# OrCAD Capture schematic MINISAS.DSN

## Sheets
1 PAGE2: size B; title: TIDA-00425; rev: A; note: 12 Gbps SAS-3 Link Extender
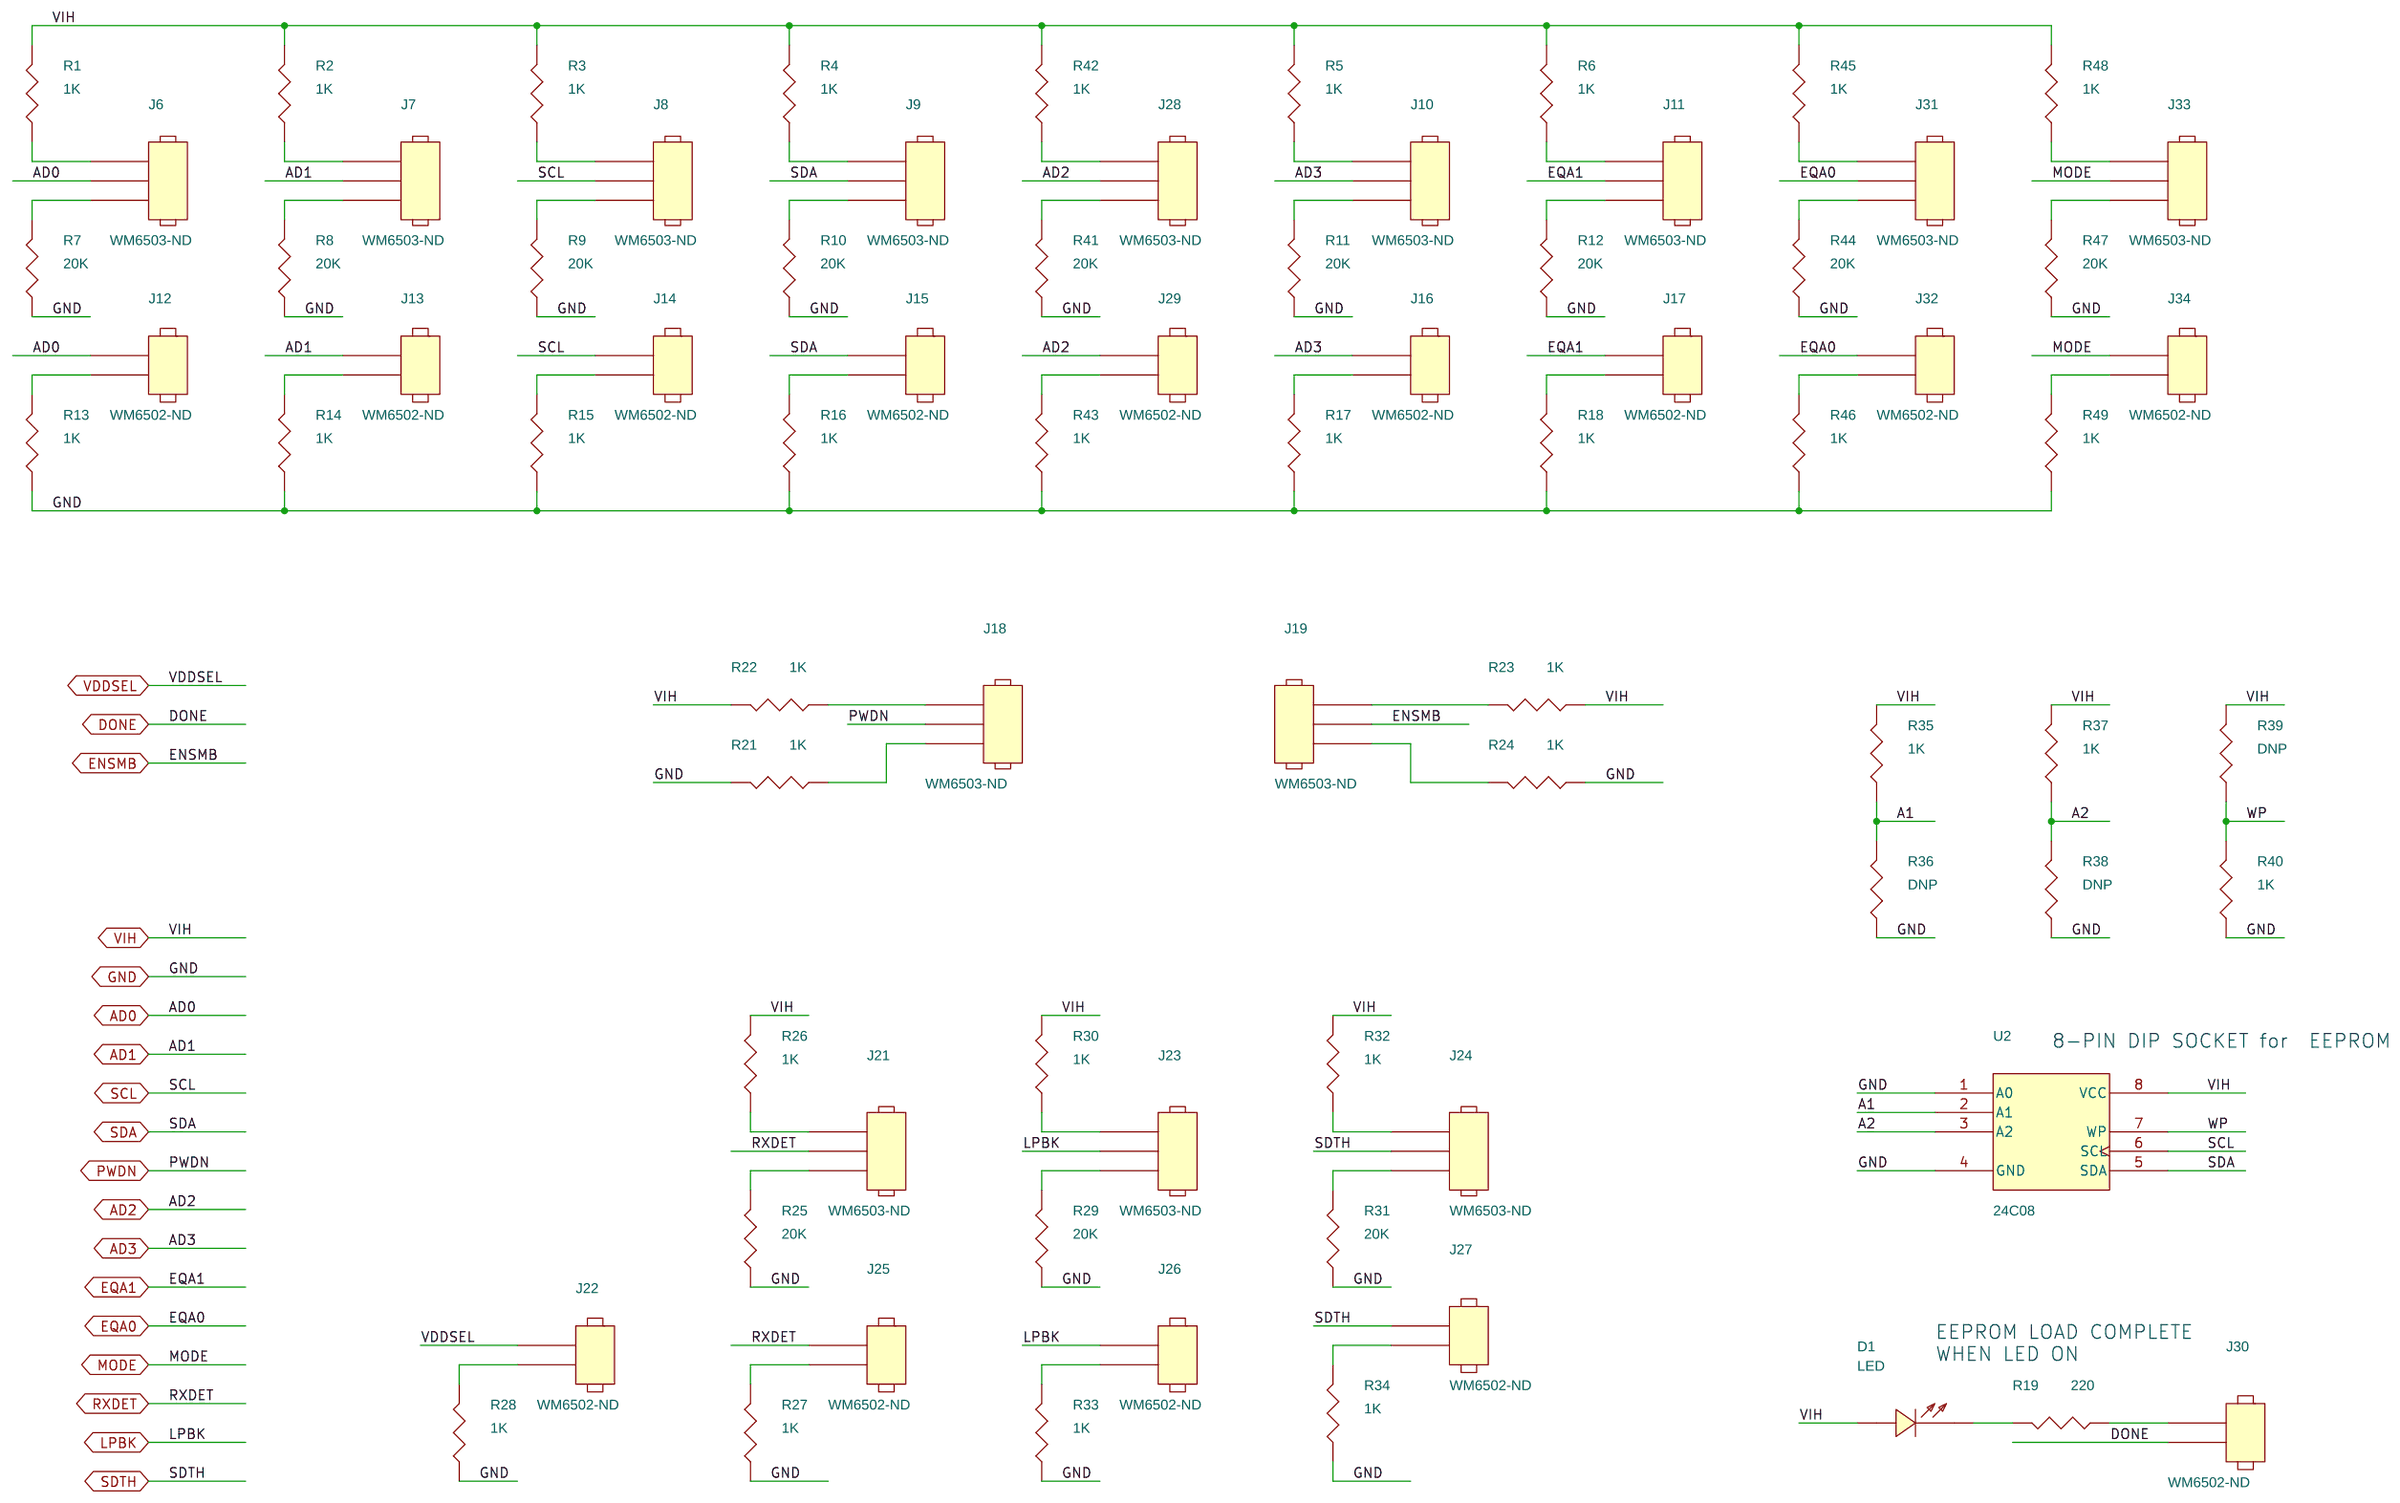
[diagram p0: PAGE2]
2 PAGE1: size B
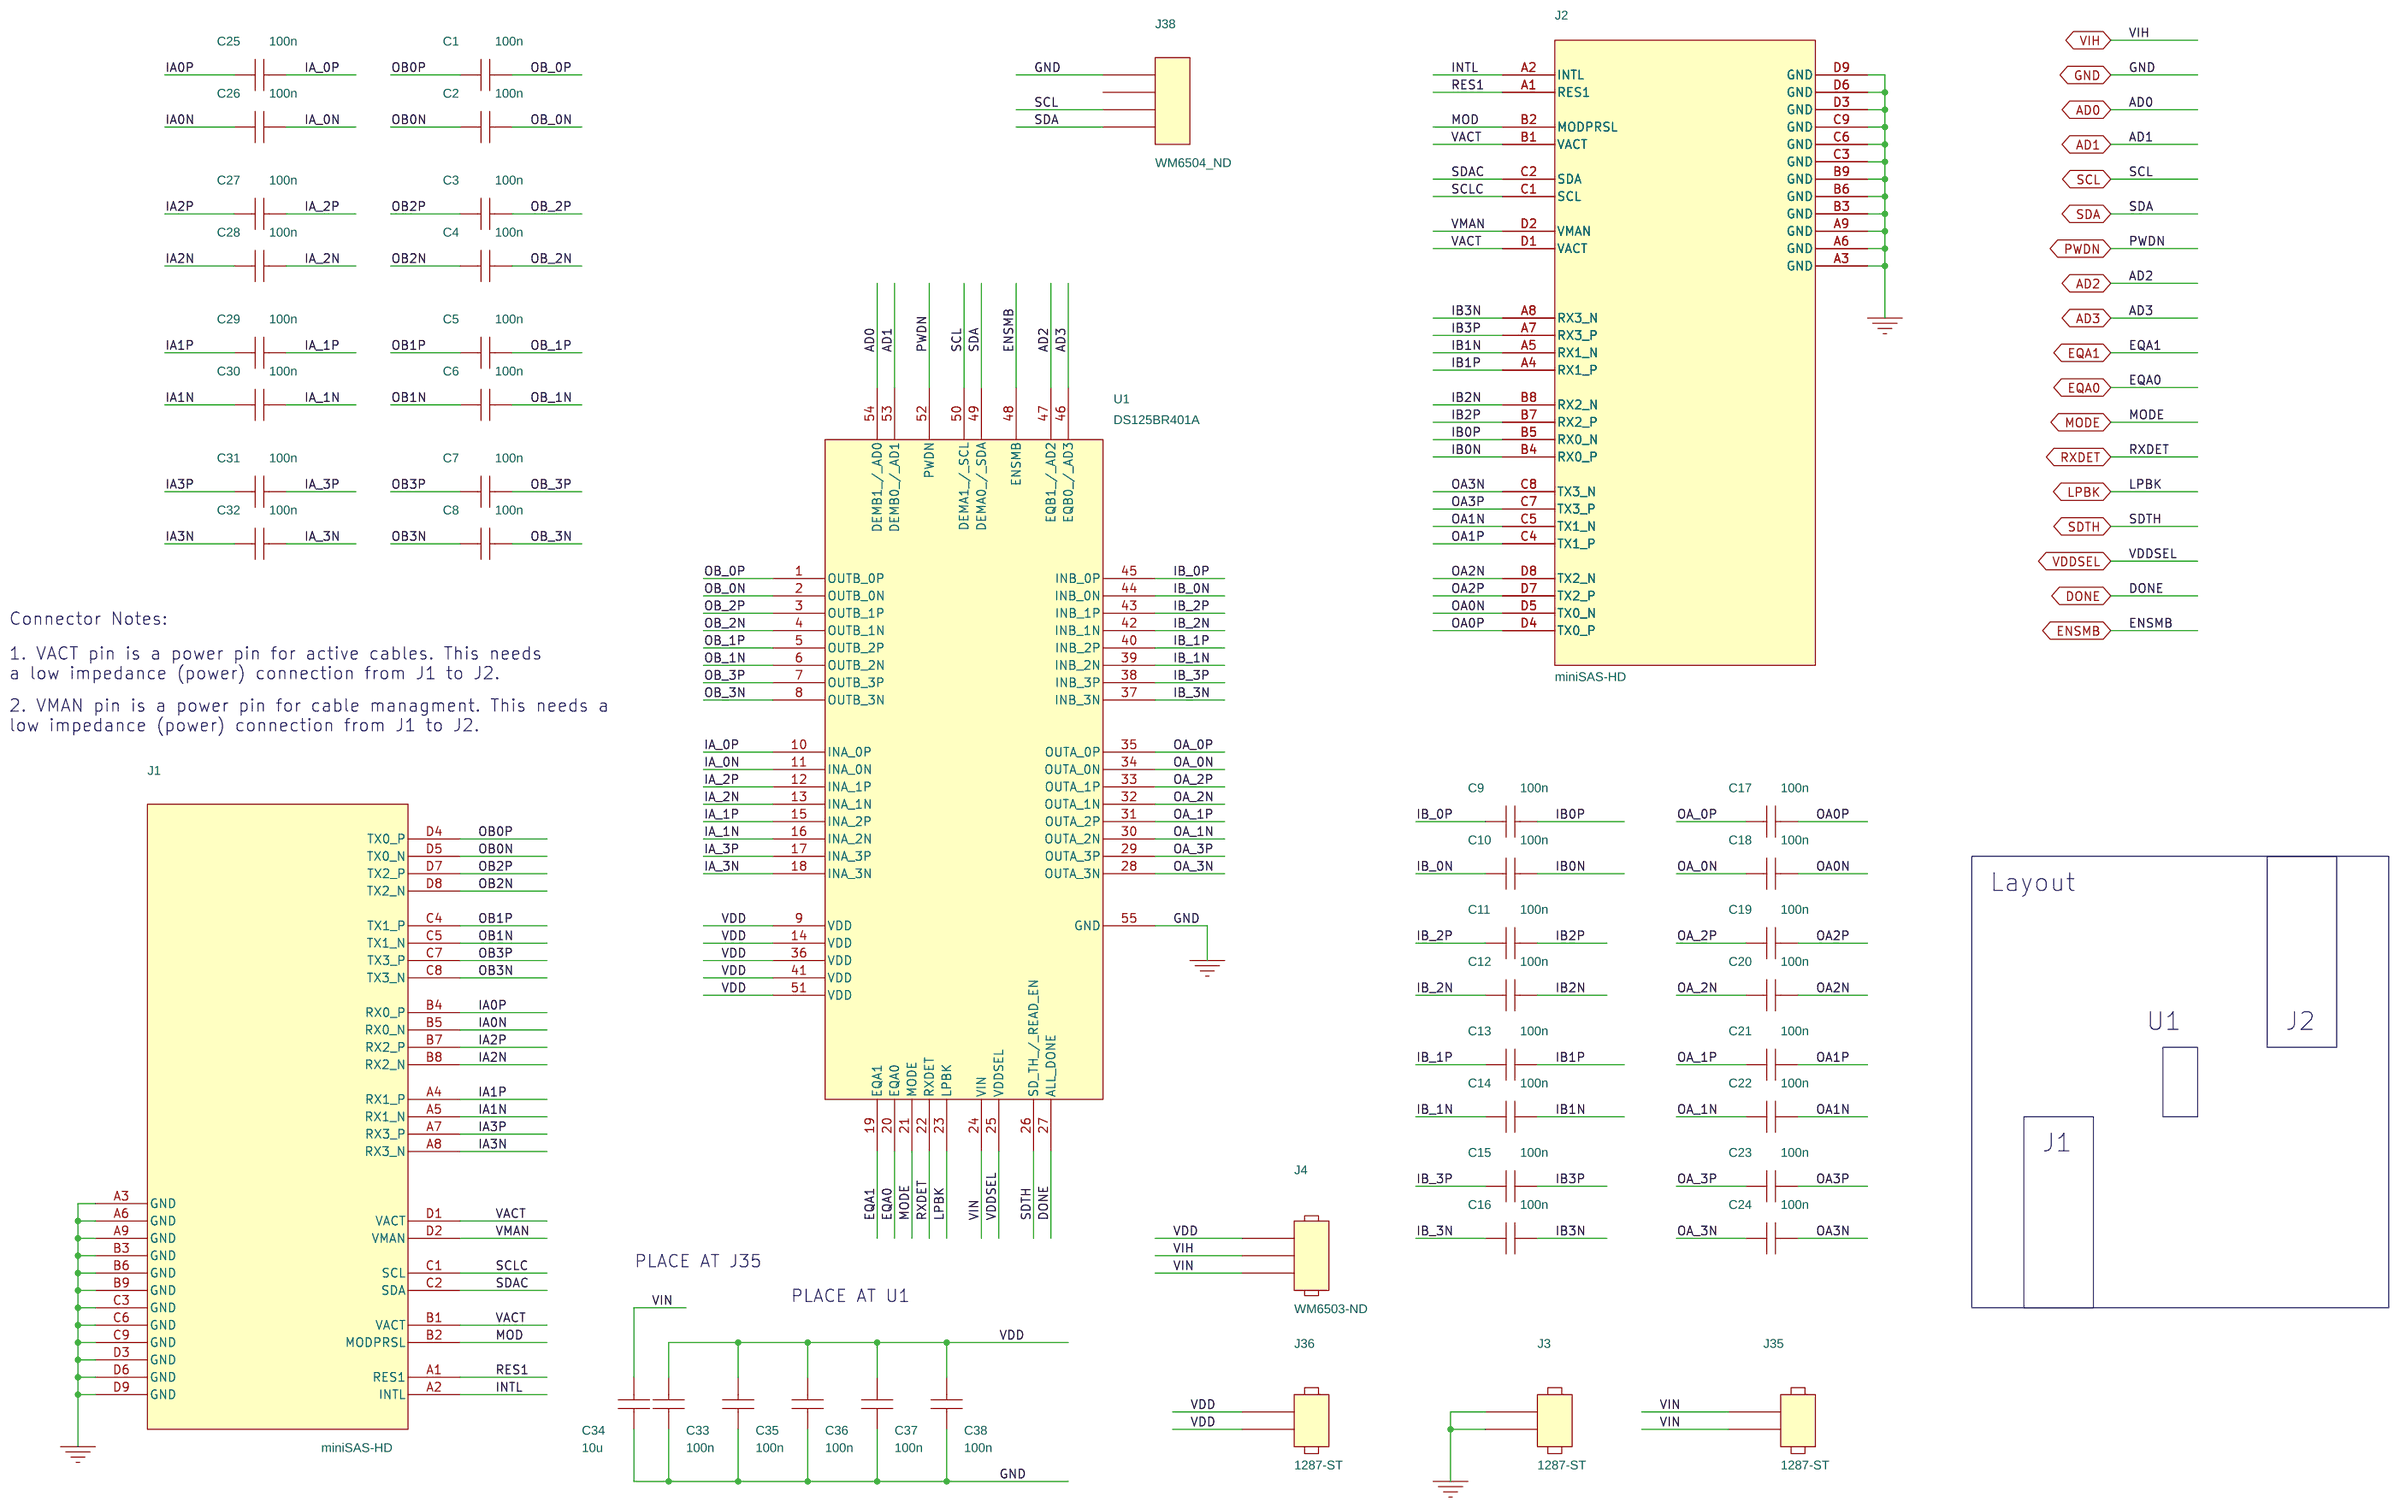
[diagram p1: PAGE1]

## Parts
sheet PAGE1
C1  100n  [0201]
C2  100n  [0201]
C3  100n  [0201]
C4  100n  [0201]
C5  100n  [0201]
C6  100n  [0201]
C7  100n  [0201]
C8  100n  [0201]
C9  100n  [0201]
C10  100n  [0201]
C11  100n  [0201]
C12  100n  [0201]
C13  100n  [0201]
C14  100n  [0201]
C15  100n  [0201]
C16  100n  [0201]
C17  100n  [0201]
C18  100n  [0201]
C19  100n  [0201]
C20  100n  [0201]
C21  100n  [0201]
C22  100n  [0201]
C23  100n  [0201]
C24  100n  [0201]
C25  100n  [0201]
C26  100n  [0201]
C27  100n  [0201]
C28  100n  [0201]
C29  100n  [0201]
C30  100n  [0201]
C31  100n  [0201]
C32  100n  [0201]
C33  100n  [0201]
C34  10u  [1206]
C35  100n  [0201]
C36  100n  [0201]
C37  100n  [0201]
C38  100n  [0201]
J1  miniSAS-HD  [minisashd]
J2  miniSAS-HD  [minisashd]
J3  1287-ST  [1287ST]
J4  WM6503-ND  [HEADER3]
J35  1287-ST  [1287ST]
J36  1287-ST  [1287ST]
J38  WM6504_ND  [HEADER4]
U1  DS125BR401A  [QFN54]
sheet PAGE2
D1  LED  [0603]
J6  WM6503-ND  [HEADER3]
J7  WM6503-ND  [HEADER3]
J8  WM6503-ND  [HEADER3]
J9  WM6503-ND  [HEADER3]
J10  WM6503-ND  [HEADER3]
J11  WM6503-ND  [HEADER3]
J12  WM6502-ND  [HEADER2]
J13  WM6502-ND  [HEADER2]
J14  WM6502-ND  [HEADER2]
J15  WM6502-ND  [HEADER2]
J16  WM6502-ND  [HEADER2]
J17  WM6502-ND  [HEADER2]
J18  WM6503-ND  [HEADER3]
J19  WM6503-ND  [HEADER3]
J21  WM6503-ND  [HEADER3]
J22  WM6502-ND  [HEADER2]
J23  WM6503-ND  [HEADER3]
J24  WM6503-ND  [HEADER3]
J25  WM6502-ND  [HEADER2]
J26  WM6502-ND  [HEADER2]
J27  WM6502-ND  [HEADER2]
J28  WM6503-ND  [HEADER3]
J29  WM6502-ND  [HEADER2]
J30  WM6502-ND  [HEADER2]
J31  WM6503-ND  [HEADER3]
J32  WM6502-ND  [HEADER2]
J33  WM6503-ND  [HEADER3]
J34  WM6502-ND  [HEADER2]
R1  1K  [0402]
R2  1K  [0402]
R3  1K  [0402]
R4  1K  [0402]
R5  1K  [0402]
R6  1K  [0402]
R7  20K  [0402]
R8  20K  [0402]
R9  20K  [0402]
R10  20K  [0402]
R11  20K  [0402]
R12  20K  [0402]
R13  1K  [0402]
R14  1K  [0402]
R15  1K  [0402]
R16  1K  [0402]
R17  1K  [0402]
R18  1K  [0402]
R19  220  [0402]
R21  1K  [0402]
R22  1K  [0402]
R23  1K  [0402]
R24  1K  [0402]
R25  20K  [0402]
R26  1K  [0402]
R27  1K  [0402]
R28  1K  [0402]
R29  20K  [0402]
R30  1K  [0402]
R31  20K  [0402]
R32  1K  [0402]
R33  1K  [0402]
R34  1K  [0402]
R35  1K  [0402]
R36  DNP  [0402]
R37  1K  [0402]
R38  DNP  [0402]
R39  DNP  [0402]
R40  1K  [0402]
R41  20K  [0402]
R42  1K  [0402]
R43  1K  [0402]
R44  20K  [0402]
R45  1K  [0402]
R46  1K  [0402]
R47  20K  [0402]
R48  1K  [0402]
R49  1K  [0402]
U2  24C08  [DIP8-SMT]

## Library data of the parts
C1-C38 = CAP_NP
J1 J2 = HEADER_40_1
J3 J35 J36 = CONN_PWR_2-P
J4 J6-J11 J18 J19 J21 J23 J24 J28 J31 J33 = CONN_PLUG_3
J38 = CON4
U1 = DS3486_SO_2
D1 = LED
J12-J17 J22 J25-J27 J29 J30 J32 J34 = CONN_PLUG_2
R1-R19 R21-R49 = R
U2 = 24C08

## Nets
GND: C33.1 C34.1 C35.1 C36.1 C37.1 C38.1 J1.A3(GND) J1.A6(GND) J1.A9(GND) J1.B3(GND) J1.B6(GND) J1.B9(GND) J1.C3(GND) J1.C6(GND) J1.C9(GND) J1.D3(GND) J1.D6(GND) J1.D9(GND) J2.A3(GND) J2.A6(GND) J2.A9(GND) J2.B3(GND) J2.B6(GND) J2.B9(GND) J2.C3(GND) J2.C6(GND) J2.C9(GND) J2.D3(GND) J2.D6(GND) J2.D9(GND) J3.1 J3.2 J38.1 R7.1 R8.1 R9.1 R10.1 R11.1 R12.1 R13.1 R14.1 R15.1 R16.1 R17.1 R18.1 R21.2 R24.1 R25.1 R27.1 R28.1 R29.1 R31.1 R33.1 R34.1 R36.1 R38.1 R40.1 R41.1 R43.1 R44.1 R46.1 R47.1 R49.1 U1.55(GND) U2.1(A0) U2.4(GND)
VDD: C33.2 C35.2 C36.2 C37.2 C38.2 J4.1 J36.1 J36.2 U1.9(VDD) U1.14(VDD) U1.36(VDD) U1.41(VDD) U1.51(VDD)
VDDSEL: J22.1 U1.25(VDDSEL)
VIN: C34.2 J4.3 J35.1 J35.2 U1.24(VIN)
A1: R35.1 R36.2 U2.2(A1)
A2: R37.1 R38.2 U2.3(A2)
AD0: J6.2 J12.1 U1.54(DEMB1_/_AD0)
AD1: J7.2 J13.1 U1.53(DEMB0_/_AD1)
AD2: J28.2 J29.1 U1.47(EQB1_/_AD2)
AD3: J10.2 J16.1 U1.46(EQB0_/_AD3)
DONE: J30.2 U1.27(ALL_DONE)
ENSMB: J19.2 U1.48(ENSMB)
EQA0: J31.2 J32.1 U1.20(EQA0)
EQA1: J11.2 J17.1 U1.19(EQA1)
IA0N: C26.1 J1.B5(RX0_N)
IA0P: C25.1 J1.B4(RX0_P)
IA1N: C30.1 J1.A5(RX1_N)
IA1P: C29.1 J1.A4(RX1_P)
IA2N: C28.1 J1.B8(RX2_N)
IA2P: C27.1 J1.B7(RX2_P)
IA3N: C32.1 J1.A8(RX3_N)
IA3P: C31.1 J1.A7(RX3_P)
IA_0N: C26.2 U1.11(INA_0N)
IA_0P: C25.2 U1.10(INA_0P)
IA_1N: C30.2 U1.16(INA_2N)
IA_1P: C29.2 U1.15(INA_2P)
IA_2N: C28.2 U1.13(INA_1N)
IA_2P: C27.2 U1.12(INA_1P)
IA_3N: C32.2 U1.18(INA_3N)
IA_3P: C31.2 U1.17(INA_3P)
IB0N: C10.2 J2.B4(RX0_P)
IB0P: C9.2 J2.B5(RX0_N)
IB1N: C14.2 J2.A5(RX1_N)
IB1P: C13.2 J2.A4(RX1_P)
IB2N: C12.2 J2.B8(RX2_N)
IB2P: C11.2 J2.B7(RX2_P)
IB3N: C16.2 J2.A8(RX3_N)
IB3P: C15.2 J2.A7(RX3_P)
IB_0N: C10.1 U1.44(INB_0N)
IB_0P: C9.1 U1.45(INB_0P)
IB_1N: C14.1 U1.39(INB_2N)
IB_1P: C13.1 U1.40(INB_2P)
IB_2N: C12.1 U1.42(INB_1N)
IB_2P: C11.1 U1.43(INB_1P)
IB_3N: C16.1 U1.37(INB_3N)
IB_3P: C15.1 U1.38(INB_3P)
INTL: J1.A2(INTL) J2.A2(INTL)
LPBK: J23.2 J26.1 U1.23(LPBK)
MOD: J1.B2(MODPRSL) J2.B2(MODPRSL)
MODE: J33.2 J34.1 U1.21(MODE)
OA0N: C18.2 J2.D5(TX0_N)
OA0P: C17.2 J2.D4(TX0_P)
OA1N: C22.2 J2.C5(TX1_N)
OA1P: C21.2 J2.C4(TX1_P)
OA2N: C20.2 J2.D8(TX2_N)
OA2P: C19.2 J2.D7(TX2_P)
OA3N: C24.2 J2.C8(TX3_N)
OA3P: C23.2 J2.C7(TX3_P)
OA_0N: C18.1 U1.34(OUTA_0N)
OA_0P: C17.1 U1.35(OUTA_0P)
OA_1N: C22.1 U1.30(OUTA_2N)
OA_1P: C21.1 U1.31(OUTA_2P)
OA_2N: C20.1 U1.32(OUTA_1N)
OA_2P: C19.1 U1.33(OUTA_1P)
OA_3N: C24.1 U1.28(OUTA_3N)
OA_3P: C23.1 U1.29(OUTA_3P)
OB0N: C2.1 J1.D5(TX0_N)
OB0P: C1.1 J1.D4(TX0_P)
OB1N: C6.1 J1.C5(TX1_N)
OB1P: C5.1 J1.C4(TX1_P)
OB2N: C4.1 J1.D8(TX2_N)
OB2P: C3.1 J1.D7(TX2_P)
OB3N: C8.1 J1.C8(TX3_N)
OB3P: C7.1 J1.C7(TX3_P)
OB_0N: C2.2 U1.2(OUTB_0N)
OB_0P: C1.2 U1.1(OUTB_0P)
OB_1N: C6.2 U1.6(OUTB_2N)
OB_1P: C5.2 U1.5(OUTB_2P)
OB_2N: C4.2 U1.4(OUTB_1N)
OB_2P: C3.2 U1.3(OUTB_1P)
OB_3N: C8.2 U1.8(OUTB_3N)
OB_3P: C7.2 U1.7(OUTB_3P)
PWDN: J18.2 U1.52(PWDN)
RES1: J1.A1(RES1) J2.A1(RES1)
RXDET: J21.2 J25.1 U1.22(RXDET)
SCL: J8.2 J14.1 J38.3 U1.50(DEMA1_/_SCL) U2.6(SCL)
SCLC: J1.C1(SCL) J2.C1(SCL)
SDA: J9.2 J15.1 J38.4 U1.49(DEMA0_/_SDA) U2.5(SDA)
SDAC: J1.C2(SDA) J2.C2(SDA)
SDTH: J24.2 J27.1 U1.26(SD_TH_/_READ_EN)
VACT: J1.B1(VACT) J1.D1(VACT) J2.B1(VACT) J2.D1(VACT)
VIH: D1.1(ANODE) J4.2 R1.2 R2.2 R3.2 R4.2 R5.2 R6.2 R22.2 R23.1 R26.2 R30.2 R32.2 R35.2 R37.2 R39.2 R42.2 R45.2 R48.2 U2.8(VCC)
VMAN: J1.D2(VMAN) J2.D2(VMAN)
WP: R39.1 R40.2 U2.7(WP)
N469503: J6.3 R7.2
N469537: D1.2(CATHODE) R19.2
N469595: J6.1 R1.1
N469811: J7.3 R8.2
N469819: J8.3 R9.2
N469827: J9.3 R10.2
N469835: J10.3 R11.2
N469843: J11.3 R12.2
N469847: J10.1 R5.1
N469855: J11.1 R6.1
N469867: J9.1 R4.1
N469875: J8.1 R3.1
N469883: J7.1 R2.1
N469925: J13.2 R14.2
N469953: J12.2 R13.2
N469977: J14.2 R15.2
N470001: J15.2 R16.2
N470025: J16.2 R17.2
N470049: J17.2 R18.2
N470163: J30.1 R19.1
N470231: J18.1 R22.1
N470235: J18.3 R21.1
N470313: J19.1 R23.2
N470329: J19.3 R24.2
N470353: J21.3 R25.2
N470405: J21.1 R26.1
N470413: J25.2 R27.2
N470453: J22.2 R28.2
N470501: J23.3 R29.2
N470525: J23.1 R30.1
N470567: J24.3 R31.2
N470597: J24.1 R32.1
N470693: J27.2 R34.2
N470705: J26.2 R33.2
N472799: J28.3 R41.2
N472807: J28.1 R42.1
N472815: J29.2 R43.2
N477528: J31.3 R44.2
N477536: J31.1 R45.1
N477544: J32.2 R46.2
N478062: J33.3 R47.2
N478086: J33.1 R48.1
N478094: J34.2 R49.2

Not connected (* = marked no-connect by the designer): J38 2

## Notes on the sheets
sheet 1
- 8-PIN DIP SOCKET for  EEPROM
- EEPROM LOAD COMPLETE
  WHEN LED ON
sheet 2
- Connector Notes:
- 1. VACT pin is a power pin for active cables. This needs
  a low impedance (power) connection from J1 to J2.
- 2. VMAN pin is a power pin for cable managment. This needs a
  low impedance (power) connection from J1 to J2.
- Layout
- U1
- J2
- J1
- PLACE AT J35
- PLACE AT U1
